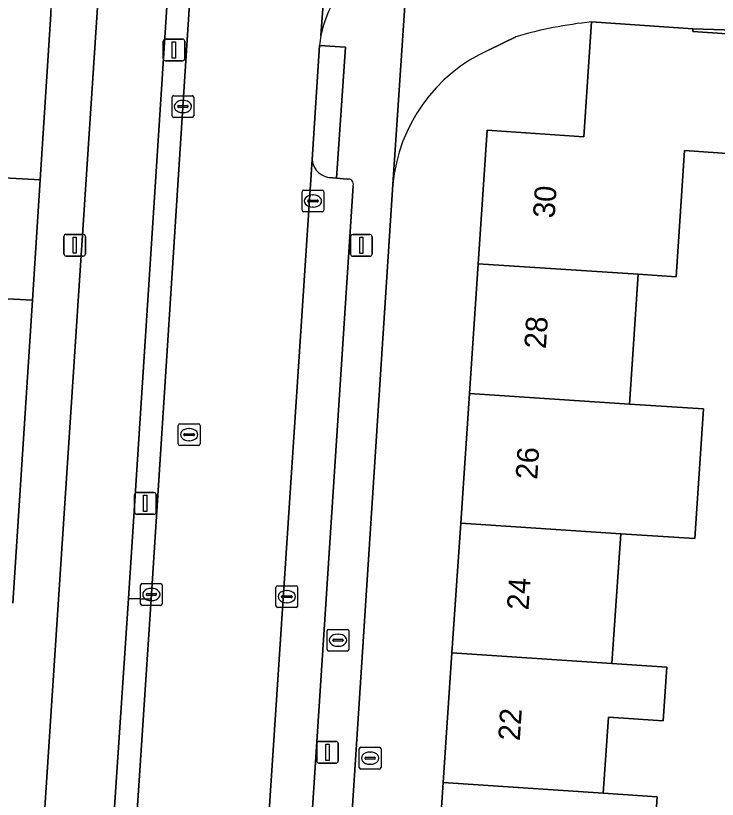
# Model space of a CAD drawing. Extents: x 161848 to 162726, y 385382 to 386521.
# Drawn here: x 162009.2 to 162041.55, y 385704.61 to 385740.75 of the extents above; entities that cross this region are included whole.
import ezdxf

# ---------------------------------------------------------------- set-up
doc = ezdxf.new("R2010")
doc.units = 0
for name, color, linetype in [('IMGEO_Berm_groen', 7, 'Continuous'), ('IMGEO_Brandkraan', 7, 'Continuous'), ('IMGEO_Erf', 7, 'Continuous'), ('IMGEO_Fietspad_gesloten', 7, 'Continuous'), ('IMGEO_Groenvoorziening', 7, 'Continuous'), ('IMGEO_Kolk', 7, 'Continuous'), ('IMGEO_Lichtmast', 7, 'Continuous'), ('IMGEO_Muur', 7, 'Continuous'), ('IMGEO_Pand', 7, 'Continuous'), ('IMGEO_Pand_nummerreeks', 7, 'Continuous'), ('IMGEO_Parkeervlak_open', 7, 'Continuous'), ('IMGEO_Rijbaan_lokaal_open', 7, 'Continuous'), ('IMGEO_Rioolput', 7, 'Continuous'), ('IMGEO_Verkeerseiland_open', 7, 'Continuous'), ('IMGEO_Voetpad_op_trap', 7, 'Continuous'), ('IMGEO_Voetpad_open', 7, 'Continuous')]:
    doc.layers.add(name, color=color, linetype=linetype)

msp = doc.modelspace()

# ---------------------------------------------------------------- linework, layer by layer
at = {"layer": 'IMGEO_Berm_groen'}
msp.add_lwpolyline([(162010.52, 385742.756), (161990.837, 385744.335), (161971.9, 385746.225), (161952.944, 385747.799), (161952.493, 385741.71), (161971.704, 385740.493), (162006.281, 385737.975), (162005.981, 385733.434), (162007.276, 385733.35), (162010.327, 385733.184), (162010.817, 385740.826), (162010.828, 385740.989)], dxfattribs=at)
at = {"layer": 'IMGEO_Brandkraan'}
for p, q in [((162023.561, 385711.518), (162023.561, 385712.37)), ((162023.636, 385712.444), (162024.488, 385712.444)), ((162024.049, 385712.224), (162024.074, 385712.224)), ((162024.562, 385712.37), (162024.562, 385711.518)), ((162023.82, 385711.938), (162023.82, 385711.95)), ((162024.258, 385711.901), (162023.86, 385711.901)), ((162023.863, 385711.987), (162024.261, 385711.987)), ((162024.304, 385711.95), (162024.304, 385711.938)), ((162024.072, 385711.664), (162024.047, 385711.664)), ((162024.488, 385711.444), (162023.636, 385711.444))]:
    msp.add_line(p, q, dxfattribs=at)
for points in [[(162023.561, 385711.518), (162023.561, 385712.37)], [(162023.636, 385712.444), (162024.488, 385712.444)], [(162024.562, 385712.37), (162024.562, 385711.518)], [(162024.488, 385711.444), (162023.636, 385711.444)]]:
    msp.add_lwpolyline(points, dxfattribs=at)
for centre, radius, start, end in [((162023.638, 385712.368), 0.0765, 91.552, 178.448), ((162023.638, 385712.368), 0.0765, 91.552, 178.448), ((162024.486, 385712.368), 0.0765, 1.552, 88.448), ((162024.486, 385712.368), 0.0765, 1.552, 88.448), ((162023.86, 385711.947), 0.0403, 85.8775, 175.7526), ((162023.857, 385711.937), 0.0366, 178.938, 274.7102), ((162024.261, 385711.944), 0.043, 264.8664, 352.4533), ((162024.265, 385711.949), 0.0386, 1.7309, 96.639), ((162023.638, 385711.52), 0.0765, 181.552, 268.448), ((162023.638, 385711.52), 0.0765, 181.552, 268.448), ((162024.486, 385711.52), 0.0765, 271.552, 358.448), ((162024.486, 385711.52), 0.0765, 271.552, 358.448)]:
    msp.add_arc(centre, radius, start, end, dxfattribs=at)
for centre, major_axis, ratio, start_param, end_param in [((162024.048, 385711.944), (-0.387, 0.002), 0.722429, 4.712389, 7.853982), ((162024.073, 385711.944), (-0.39, 0.002), 0.717154, 1.570796, 4.712389)]:
    msp.add_ellipse(centre, major_axis=major_axis, ratio=ratio, start_param=start_param, end_param=end_param, dxfattribs=at)
at = {"layer": 'IMGEO_Erf'}
for points in [[(162028.509, 385699.399), (162028.911, 385705.382), (162029.313, 385711.364), (162029.716, 385717.347), (162030.118, 385723.329), (162030.52, 385729.311), (162030.934, 385735.462), (162035.394, 385735.162), (162035.75, 385740.46)], [(162045.739, 385739.976), (162040.42, 385740.146), (162040.411, 385740.016), (162045.621, 385739.663)], [(162032.253, 385739.775), (162031.023, 385739.175)], [(162045.298, 385734.167), (162040.038, 385734.524), (162039.643, 385728.704), (162037.897, 385728.82), (162037.495, 385722.838), (162040.906, 385722.611), (162040.508, 385716.629), (162037.092, 385716.856), (162036.69, 385710.873), (162039.215, 385710.705), (162039.051, 385708.232), (162036.523, 385708.4), (162036.287, 385704.891), (162038.781, 385704.725), (162038.379, 385698.742)], [(162026.588, 385732.967), (162023.994, 385692.934)]]:
    msp.add_lwpolyline(points, dxfattribs=at)
for centre, radius, start, end in [((162037.663, 385721.425), 19.131, 95.7389, 106.4269), ((162034.162, 385732.245), 7.608, 114.3648, 174.5512)]:
    msp.add_arc(centre, radius, start, end, dxfattribs=at)
at = {"layer": 'IMGEO_Fietspad_gesloten'}
msp.add_lwpolyline([(162013.158, 385743.949), (162010.873, 385709.146), (162010.549, 385704.218), (162010.295, 385700.348), (162010.217, 385699.151), (162008.977, 385680.053), (162008.886, 385678.416), (162007.821, 385663.003), (162007.424, 385657.272), (162006.576, 385645.271), (162006.478, 385643.76), (162005.344, 385626.899), (162005.265, 385625.346), (162004.604, 385615.402), (162004.294, 385610.839), (162003.948, 385605.742), (162007.138, 385605.527), (162007.893, 385616.747), (162013.268, 385696.929), (162014.399, 385713.867), (162016.417, 385744.964)], dxfattribs=at)
at = {"layer": 'IMGEO_Groenvoorziening'}
msp.add_lwpolyline([(162009.076, 385713.656), (162009.972, 385727.634), (162005.39, 385727.881), (162004.634, 385716.496), (162004.404, 385714.393), (162004.317, 385711.964), (162006.96, 385711.781)], dxfattribs=at)
at = {"layer": 'IMGEO_Kolk'}
for p, q in [((162016.412, 385736.134), (162016.412, 385736.986)), ((162016.487, 385737.06), (162017.339, 385737.06)), ((162016.9, 385736.84), (162016.925, 385736.84)), ((162017.413, 385736.986), (162017.413, 385736.134)), ((162016.671, 385736.554), (162016.671, 385736.566)), ((162017.109, 385736.517), (162016.711, 385736.517)), ((162016.714, 385736.603), (162017.112, 385736.603)), ((162017.155, 385736.566), (162017.155, 385736.554)), ((162016.923, 385736.28), (162016.898, 385736.28)), ((162017.339, 385736.06), (162016.487, 385736.06)), ((162022.405, 385731.775), (162022.405, 385732.627)), ((162022.48, 385732.701), (162023.332, 385732.701)), ((162022.893, 385732.481), (162022.918, 385732.481)), ((162023.406, 385732.627), (162023.406, 385731.775)), ((162022.664, 385732.195), (162022.664, 385732.207)), ((162023.102, 385732.158), (162022.704, 385732.158)), ((162022.707, 385732.244), (162023.105, 385732.244)), ((162023.148, 385732.207), (162023.148, 385732.195)), ((162022.916, 385731.921), (162022.891, 385731.921)), ((162023.332, 385731.701), (162022.48, 385731.701)), ((162014.959, 385713.627), (162014.959, 385714.479)), ((162015.034, 385714.553), (162015.886, 385714.553)), ((162015.96, 385714.479), (162015.96, 385713.627)), ((162021.276, 385714.455), (162022.128, 385714.455)), ((162015.218, 385714.047), (162015.218, 385714.059)), ((162015.261, 385714.096), (162015.659, 385714.096)), ((162015.447, 385714.333), (162015.472, 385714.333)), ((162015.702, 385714.059), (162015.702, 385714.047)), ((162021.201, 385713.529), (162021.201, 385714.381)), ((162021.689, 385714.235), (162021.714, 385714.235)), ((162022.202, 385714.381), (162022.202, 385713.529)), ((162015.656, 385714.01), (162015.258, 385714.01)), ((162015.47, 385713.773), (162015.445, 385713.773)), ((162021.46, 385713.949), (162021.46, 385713.961)), ((162021.898, 385713.912), (162021.5, 385713.912)), ((162021.503, 385713.998), (162021.901, 385713.998)), ((162021.712, 385713.675), (162021.687, 385713.675)), ((162021.944, 385713.961), (162021.944, 385713.949)), ((162015.886, 385713.553), (162015.034, 385713.553)), ((162022.128, 385713.455), (162021.276, 385713.455))]:
    msp.add_line(p, q, dxfattribs=at)
for points in [[(162016.412, 385736.134), (162016.412, 385736.986)], [(162016.487, 385737.06), (162017.339, 385737.06)], [(162017.413, 385736.986), (162017.413, 385736.134)], [(162017.339, 385736.06), (162016.487, 385736.06)], [(162022.405, 385731.775), (162022.405, 385732.627)], [(162022.48, 385732.701), (162023.332, 385732.701)], [(162023.406, 385732.627), (162023.406, 385731.775)], [(162023.332, 385731.701), (162022.48, 385731.701)], [(162014.959, 385713.627), (162014.959, 385714.479)], [(162015.034, 385714.553), (162015.886, 385714.553)], [(162015.96, 385714.479), (162015.96, 385713.627)], [(162021.276, 385714.455), (162022.128, 385714.455)], [(162021.201, 385713.529), (162021.201, 385714.381)], [(162022.202, 385714.381), (162022.202, 385713.529)], [(162015.886, 385713.553), (162015.034, 385713.553)], [(162022.128, 385713.455), (162021.276, 385713.455)]]:
    msp.add_lwpolyline(points, dxfattribs=at)
for centre, radius, start, end in [((162016.489, 385736.984), 0.0765, 91.552, 178.448), ((162016.489, 385736.984), 0.0765, 91.552, 178.448), ((162017.337, 385736.984), 0.0765, 1.552, 88.448), ((162017.337, 385736.984), 0.0765, 1.552, 88.448), ((162016.711, 385736.563), 0.0403, 85.8775, 175.7526), ((162016.708, 385736.553), 0.0366, 178.938, 274.7102), ((162017.112, 385736.56), 0.043, 264.8664, 352.4533), ((162017.116, 385736.565), 0.0386, 1.7309, 96.639), ((162016.489, 385736.136), 0.0765, 181.552, 268.448), ((162016.489, 385736.136), 0.0765, 181.552, 268.448), ((162017.337, 385736.136), 0.0765, 271.552, 358.448), ((162017.337, 385736.136), 0.0765, 271.552, 358.448), ((162022.482, 385732.625), 0.0765, 91.552, 178.448), ((162022.482, 385732.625), 0.0765, 91.552, 178.448), ((162023.33, 385732.625), 0.0765, 1.552, 88.448), ((162023.33, 385732.625), 0.0765, 1.552, 88.448), ((162022.704, 385732.204), 0.0403, 85.8775, 175.7526), ((162022.701, 385732.194), 0.0366, 178.938, 274.7102), ((162023.105, 385732.201), 0.043, 264.8664, 352.4533), ((162023.109, 385732.206), 0.0386, 1.7309, 96.639), ((162022.482, 385731.777), 0.0765, 181.552, 268.448), ((162022.482, 385731.777), 0.0765, 181.552, 268.448), ((162023.33, 385731.777), 0.0765, 271.552, 358.448), ((162023.33, 385731.777), 0.0765, 271.552, 358.448), ((162015.036, 385714.477), 0.0765, 91.552, 178.448), ((162015.036, 385714.477), 0.0765, 91.552, 178.448), ((162015.884, 385714.477), 0.0765, 1.552, 88.448), ((162015.884, 385714.477), 0.0765, 1.552, 88.448), ((162021.278, 385714.379), 0.0765, 91.552, 178.448), ((162021.278, 385714.379), 0.0765, 91.552, 178.448), ((162022.126, 385714.379), 0.0765, 1.552, 88.448), ((162022.126, 385714.379), 0.0765, 1.552, 88.448), ((162015.258, 385714.056), 0.0403, 85.8775, 175.7526), ((162015.255, 385714.046), 0.0366, 178.938, 274.7102), ((162015.659, 385714.053), 0.043, 264.8664, 352.4533), ((162015.663, 385714.058), 0.0386, 1.7309, 96.639), ((162021.5, 385713.958), 0.0403, 85.8775, 175.7526), ((162021.497, 385713.948), 0.0366, 178.938, 274.7102), ((162021.901, 385713.955), 0.043, 264.8664, 352.4533), ((162021.905, 385713.96), 0.0386, 1.7309, 96.639), ((162015.036, 385713.629), 0.0765, 181.552, 268.448), ((162015.036, 385713.629), 0.0765, 181.552, 268.448), ((162015.884, 385713.629), 0.0765, 271.552, 358.448), ((162015.884, 385713.629), 0.0765, 271.552, 358.448), ((162021.278, 385713.531), 0.0765, 181.552, 268.448), ((162021.278, 385713.531), 0.0765, 181.552, 268.448), ((162022.126, 385713.531), 0.0765, 271.552, 358.448), ((162022.126, 385713.531), 0.0765, 271.552, 358.448)]:
    msp.add_arc(centre, radius, start, end, dxfattribs=at)
for centre, major_axis, ratio, start_param, end_param in [((162016.899, 385736.56), (-0.387, 0.002), 0.722429, 4.712389, 7.853982), ((162016.924, 385736.56), (-0.39, 0.002), 0.717154, 1.570796, 4.712389), ((162022.892, 385732.201), (-0.387, 0.002), 0.722429, 4.712389, 7.853982), ((162022.917, 385732.201), (-0.39, 0.002), 0.717154, 1.570796, 4.712389), ((162015.446, 385714.053), (-0.387, 0.002), 0.722429, 4.712389, 7.853982), ((162015.471, 385714.053), (-0.39, 0.002), 0.717154, 1.570796, 4.712389), ((162021.688, 385713.955), (-0.387, 0.002), 0.722429, 4.712389, 7.853982), ((162021.713, 385713.955), (-0.39, 0.002), 0.717154, 1.570796, 4.712389)]:
    msp.add_ellipse(centre, major_axis=major_axis, ratio=ratio, start_param=start_param, end_param=end_param, dxfattribs=at)
at = {"layer": 'IMGEO_Lichtmast'}
for p, q in [((162016.005, 385738.769), (162016.005, 385739.569)), ((162016.005, 385739.569), (162016.005, 385738.769)), ((162016.105, 385739.669), (162016.895, 385739.669)), ((162016.895, 385739.669), (162016.105, 385739.669)), ((162016.995, 385739.569), (162016.995, 385738.769)), ((162016.995, 385738.769), (162016.995, 385739.569)), ((162016.895, 385738.669), (162016.105, 385738.669)), ((162016.105, 385738.669), (162016.895, 385738.669)), ((162011.529, 385730.664), (162012.319, 385730.664)), ((162012.319, 385730.664), (162011.529, 385730.664)), ((162024.742, 385730.652), (162025.532, 385730.652)), ((162025.532, 385730.652), (162024.742, 385730.652)), ((162011.429, 385729.764), (162011.429, 385730.564)), ((162011.429, 385730.564), (162011.429, 385729.764)), ((162012.419, 385730.564), (162012.419, 385729.764)), ((162012.419, 385729.764), (162012.419, 385730.564)), ((162024.642, 385729.752), (162024.642, 385730.552)), ((162024.642, 385730.552), (162024.642, 385729.752)), ((162025.632, 385730.552), (162025.632, 385729.752)), ((162025.632, 385729.752), (162025.632, 385730.552)), ((162012.319, 385729.664), (162011.529, 385729.664)), ((162011.529, 385729.664), (162012.319, 385729.664)), ((162025.532, 385729.652), (162024.742, 385729.652)), ((162024.742, 385729.652), (162025.532, 385729.652)), ((162014.783, 385718.753), (162015.573, 385718.753)), ((162015.573, 385718.753), (162014.783, 385718.753)), ((162014.683, 385717.853), (162014.683, 385718.653)), ((162014.683, 385718.653), (162014.683, 385717.853)), ((162015.673, 385718.653), (162015.673, 385717.853)), ((162015.673, 385717.853), (162015.673, 385718.653)), ((162015.573, 385717.753), (162014.783, 385717.753)), ((162014.783, 385717.753), (162015.573, 385717.753)), ((162023.082, 385706.378), (162023.082, 385707.178)), ((162023.082, 385707.178), (162023.082, 385706.378)), ((162023.182, 385707.278), (162023.972, 385707.278)), ((162023.972, 385707.278), (162023.182, 385707.278)), ((162024.072, 385707.178), (162024.072, 385706.378)), ((162024.072, 385706.378), (162024.072, 385707.178)), ((162023.972, 385706.278), (162023.182, 385706.278)), ((162023.182, 385706.278), (162023.972, 385706.278))]:
    msp.add_line(p, q, dxfattribs=at)
for points in [[(162016.425, 385739.544), (162016.575, 385739.544), (162016.575, 385738.794), (162016.425, 385738.794), (162016.425, 385739.544)], [(162011.849, 385730.539), (162011.999, 385730.539), (162011.999, 385729.789), (162011.849, 385729.789), (162011.849, 385730.539)], [(162025.062, 385730.527), (162025.212, 385730.527), (162025.212, 385729.777), (162025.062, 385729.777), (162025.062, 385730.527)], [(162015.103, 385718.628), (162015.253, 385718.628), (162015.253, 385717.878), (162015.103, 385717.878), (162015.103, 385718.628)], [(162023.502, 385707.153), (162023.652, 385707.153), (162023.652, 385706.403), (162023.502, 385706.403), (162023.502, 385707.153)]]:
    msp.add_lwpolyline(points, dxfattribs=at)
for centre, start, end in [((162016.105, 385739.569), 90, 180), ((162016.105, 385739.569), 90, 180), ((162016.895, 385739.569), 0, 90), ((162016.895, 385739.569), 360, 90), ((162016.105, 385738.769), 180, 270), ((162016.105, 385738.769), 180, 270), ((162016.895, 385738.769), 270, 0), ((162016.895, 385738.769), 270, 0), ((162011.529, 385730.564), 90, 180), ((162011.529, 385730.564), 90, 180), ((162012.319, 385730.564), 0, 90), ((162012.319, 385730.564), 360, 90), ((162024.742, 385730.552), 90, 180), ((162024.742, 385730.552), 90, 180), ((162025.532, 385730.552), 0, 90), ((162025.532, 385730.552), 360, 90), ((162011.529, 385729.764), 180, 270), ((162011.529, 385729.764), 180, 270), ((162012.319, 385729.764), 270, 0), ((162012.319, 385729.764), 270, 0), ((162024.742, 385729.752), 180, 270), ((162024.742, 385729.752), 180, 270), ((162025.532, 385729.752), 270, 0), ((162025.532, 385729.752), 270, 0), ((162014.783, 385718.653), 90, 180), ((162014.783, 385718.653), 90, 180), ((162015.573, 385718.653), 0, 90), ((162015.573, 385718.653), 360, 90), ((162014.783, 385717.853), 180, 270), ((162014.783, 385717.853), 180, 270), ((162015.573, 385717.853), 270, 0), ((162015.573, 385717.853), 270, 0), ((162023.182, 385707.178), 90, 180), ((162023.182, 385707.178), 90, 180), ((162023.972, 385707.178), 0, 90), ((162023.972, 385707.178), 360, 90), ((162023.182, 385706.378), 180, 270), ((162023.182, 385706.378), 180, 270), ((162023.972, 385706.378), 270, 0), ((162023.972, 385706.378), 270, 0)]:
    msp.add_arc(centre, 0.1, start, end, dxfattribs=at)
at = {"layer": 'IMGEO_Muur'}
msp.add_lwpolyline([(162045.739, 385739.976), (162040.42, 385740.146)], dxfattribs=at)
at = {"layer": 'IMGEO_Pand'}
for points in [[(162040.411, 385740.016), (162040.42, 385740.146), (162035.75, 385740.46), (162035.394, 385735.162), (162030.934, 385735.462), (162030.52, 385729.311), (162037.897, 385728.82), (162039.643, 385728.704), (162040.038, 385734.524), (162045.298, 385734.167), (162045.621, 385739.663)], [(162030.52, 385729.311), (162030.118, 385723.329), (162037.495, 385722.838), (162037.897, 385728.82)], [(162040.906, 385722.611), (162037.495, 385722.838), (162030.118, 385723.329), (162029.716, 385717.347), (162037.092, 385716.856), (162040.508, 385716.629)], [(162029.716, 385717.347), (162029.313, 385711.364), (162036.69, 385710.873), (162037.092, 385716.856)], [(162036.523, 385708.4), (162039.051, 385708.232), (162039.215, 385710.705), (162036.69, 385710.873), (162029.313, 385711.364), (162028.911, 385705.382), (162036.287, 385704.891)], [(162038.781, 385704.725), (162036.287, 385704.891), (162028.911, 385705.382), (162028.509, 385699.399), (162035.885, 385698.908), (162038.379, 385698.742)]]:
    msp.add_lwpolyline(points, close=True, dxfattribs=at)
at = {"layer": 'IMGEO_Parkeervlak_open'}
for points in [[(162022.867, 385734.111), (162020.357, 385695.92)], [(162024.488, 385733.207), (162023.987, 385733.26), (162023.811, 385733.278)], [(162022.415, 385696.908), (162024.76, 385732.908)]]:
    msp.add_lwpolyline(points, dxfattribs=at)
for centre, radius, start, end in [((162023.781, 385734.196), 0.918, 185.291, 271.8577), ((162024.538, 385732.98), 0.233, 342.0826, 102.503)]:
    msp.add_arc(centre, radius, start, end, dxfattribs=at)
at = {"layer": 'IMGEO_Rijbaan_lokaal_open'}
for points in [[(162028.542, 385817.36), (162031.145, 385855.667), (162031.315, 385858.297), (162025.205, 385858.754), (162024.539, 385848.984), (162023.424, 385832.28), (162022.065, 385812.169), (162021.714, 385806.937), (162019.478, 385774.254), (162018.373, 385758.189), (162018.126, 385754.834), (162017.45, 385744.89), (162015.447, 385713.845), (162014.322, 385696.873), (162011.334, 385651.941), (162017.404, 385651.53), (162017.453, 385652.249), (162019.023, 385675.529), (162020.357, 385695.92), (162022.867, 385734.111), (162023.205, 385739.378)], [(162023.276, 385739.835), (162024.688, 385758.853)], [(162024.688, 385758.853), (162023.276, 385739.835)]]:
    msp.add_lwpolyline(points, dxfattribs=at)
for centre, radius, start, end in [((162028.481, 385738.789), 5.309, 102.635, 168.6399), ((162029.079, 385738.699), 5.913, 168.9278, 173.4104)]:
    msp.add_arc(centre, radius, start, end, dxfattribs=at)
at = {"layer": 'IMGEO_Rioolput'}
for p, q in [((162016.7, 385721), (162016.7, 385721.852)), ((162016.775, 385721.926), (162017.627, 385721.926)), ((162017.188, 385721.706), (162017.213, 385721.706)), ((162017.701, 385721.852), (162017.701, 385721)), ((162016.959, 385721.42), (162016.959, 385721.432)), ((162017.397, 385721.383), (162016.999, 385721.383)), ((162017.002, 385721.469), (162017.4, 385721.469)), ((162017.443, 385721.432), (162017.443, 385721.42)), ((162017.627, 385720.926), (162016.775, 385720.926)), ((162017.211, 385721.146), (162017.186, 385721.146)), ((162025.043, 385706.078), (162025.043, 385706.93)), ((162025.118, 385707.004), (162025.97, 385707.004)), ((162026.044, 385706.93), (162026.044, 385706.078)), ((162025.302, 385706.498), (162025.302, 385706.51)), ((162025.74, 385706.461), (162025.342, 385706.461)), ((162025.345, 385706.547), (162025.743, 385706.547)), ((162025.531, 385706.784), (162025.556, 385706.784)), ((162025.786, 385706.51), (162025.786, 385706.498)), ((162025.554, 385706.224), (162025.529, 385706.224)), ((162025.97, 385706.004), (162025.118, 385706.004))]:
    msp.add_line(p, q, dxfattribs=at)
for points in [[(162016.7, 385721), (162016.7, 385721.852)], [(162016.775, 385721.926), (162017.627, 385721.926)], [(162017.701, 385721.852), (162017.701, 385721)], [(162017.627, 385720.926), (162016.775, 385720.926)], [(162025.043, 385706.078), (162025.043, 385706.93)], [(162025.118, 385707.004), (162025.97, 385707.004)], [(162026.044, 385706.93), (162026.044, 385706.078)], [(162025.97, 385706.004), (162025.118, 385706.004)]]:
    msp.add_lwpolyline(points, dxfattribs=at)
for centre, radius, start, end in [((162016.777, 385721.85), 0.0765, 91.552, 178.448), ((162016.777, 385721.85), 0.0765, 91.552, 178.448), ((162017.625, 385721.85), 0.0765, 1.552, 88.448), ((162017.625, 385721.85), 0.0765, 1.552, 88.448), ((162016.999, 385721.429), 0.0403, 85.8775, 175.7526), ((162016.996, 385721.419), 0.0366, 178.938, 274.7102), ((162017.4, 385721.426), 0.043, 264.8664, 352.4533), ((162017.404, 385721.431), 0.0386, 1.7309, 96.639), ((162016.777, 385721.002), 0.0765, 181.552, 268.448), ((162016.777, 385721.002), 0.0765, 181.552, 268.448), ((162017.625, 385721.002), 0.0765, 271.552, 358.448), ((162017.625, 385721.002), 0.0765, 271.552, 358.448), ((162025.12, 385706.928), 0.0765, 91.552, 178.448), ((162025.12, 385706.928), 0.0765, 91.552, 178.448), ((162025.968, 385706.928), 0.0765, 1.552, 88.448), ((162025.968, 385706.928), 0.0765, 1.552, 88.448), ((162025.342, 385706.507), 0.0403, 85.8775, 175.7526), ((162025.339, 385706.497), 0.0366, 178.938, 274.7102), ((162025.743, 385706.504), 0.043, 264.8664, 352.4533), ((162025.747, 385706.509), 0.0386, 1.7309, 96.639), ((162025.12, 385706.08), 0.0765, 181.552, 268.448), ((162025.12, 385706.08), 0.0765, 181.552, 268.448), ((162025.968, 385706.08), 0.0765, 271.552, 358.448), ((162025.968, 385706.08), 0.0765, 271.552, 358.448)]:
    msp.add_arc(centre, radius, start, end, dxfattribs=at)
for centre, major_axis, ratio, start_param, end_param in [((162017.187, 385721.426), (-0.387, 0.002), 0.722429, 4.712389, 7.853982), ((162017.212, 385721.426), (-0.39, 0.002), 0.717154, 1.570796, 4.712389), ((162025.53, 385706.504), (-0.387, 0.002), 0.722429, 4.712389, 7.853982), ((162025.555, 385706.504), (-0.39, 0.002), 0.717154, 1.570796, 4.712389)]:
    msp.add_ellipse(centre, major_axis=major_axis, ratio=ratio, start_param=start_param, end_param=end_param, dxfattribs=at)
at = {"layer": 'IMGEO_Verkeerseiland_open'}
msp.add_lwpolyline([(162016.417, 385744.964), (162014.399, 385713.867), (162015.447, 385713.845), (162017.45, 385744.89)], close=True, dxfattribs=at)
at = {"layer": 'IMGEO_Voetpad_op_trap'}
msp.add_lwpolyline([(162010.327, 385733.184), (162007.276, 385733.35), (162005.981, 385733.434), (162005.625, 385733.457), (162005.264, 385727.889), (162005.39, 385727.881), (162009.972, 385727.634)], close=True, dxfattribs=at)
at = {"layer": 'IMGEO_Voetpad_open'}
for points in [[(162011.21, 385746.969), (162010.828, 385740.989), (162010.817, 385740.826), (162010.327, 385733.184), (162009.972, 385727.634), (162009.076, 385713.656)], [(162010.217, 385699.151), (162010.295, 385700.348), (162010.549, 385704.218), (162010.873, 385709.146), (162013.158, 385743.949)], [(162027.32, 385743.97), (162026.588, 385732.967)], [(162026.588, 385732.967), (162027.32, 385743.97)], [(162035.75, 385740.46), (162040.42, 385740.146), (162045.739, 385739.976), (162049.431, 385739.731), (162050.825, 385739.638), (162115.981, 385735.292)], [(162031.023, 385739.175), (162032.253, 385739.775)], [(162023.811, 385733.278), (162023.987, 385733.26), (162024.402, 385739.299), (162023.205, 385739.378), (162022.867, 385734.111)], [(162023.205, 385739.378), (162024.402, 385739.299), (162023.987, 385733.26), (162024.488, 385733.207)], [(162022.11, 385696.602), (162021.408, 385696.667), (162020.942, 385689.297), (162023.749, 385689.119), (162023.994, 385692.934), (162026.588, 385732.967)], [(162024.76, 385732.908), (162022.415, 385696.908)]]:
    msp.add_lwpolyline(points, dxfattribs=at)
msp.add_lwpolyline([(162014.399, 385713.867), (162013.268, 385696.929), (162014.322, 385696.873), (162015.447, 385713.845)], close=True, dxfattribs=at)
for centre, radius, start, end in [((162028.481, 385738.789), 5.309, 102.635, 168.6399), ((162037.663, 385721.425), 19.131, 95.7389, 106.4269), ((162029.079, 385738.699), 5.913, 168.9278, 173.4104), ((162034.162, 385732.245), 7.608, 114.3648, 174.5512), ((162023.781, 385734.196), 0.918, 185.291, 271.8577), ((162024.538, 385732.98), 0.233, 342.0826, 102.503)]:
    msp.add_arc(centre, radius, start, end, dxfattribs=at)

# ---------------------------------------------------------------- texts
at = {"layer": 'IMGEO_Pand_nummerreeks'}
for s, rotation, p in [('30', 86.1958, (162034.043, 385731.389)), ('28', 86.198, (162033.642, 385725.364)), ('26', 86.1958, (162033.243, 385719.335)), ('24', 86.198, (162032.841, 385713.31)), ('22', 86.198, (162032.441, 385707.282))]:
    msp.add_text(s, height=1, rotation=rotation, dxfattribs=at).set_placement(p)

doc.saveas('drawing.dxf')
